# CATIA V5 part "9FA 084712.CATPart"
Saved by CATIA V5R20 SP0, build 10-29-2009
Part number: 9FA 084712
Revision: ANY
Definition: UNKNOWN
Nomenclature: 9FA 084712
Source: Unknown
Bounding box of the stored display mesh (mm): x -4 to 3.804, y -10 to 10, z -4 to 4
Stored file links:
  C:\Users\Utente\Desktop\IO LAVORO\3D X SITO CF\CUMSA\3D files FA\FA 0847SF\9FA 084712.CATPart

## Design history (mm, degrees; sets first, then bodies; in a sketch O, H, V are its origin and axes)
Body1 "Cortar-Extruir5" (main body)
  Solid1: solid without history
